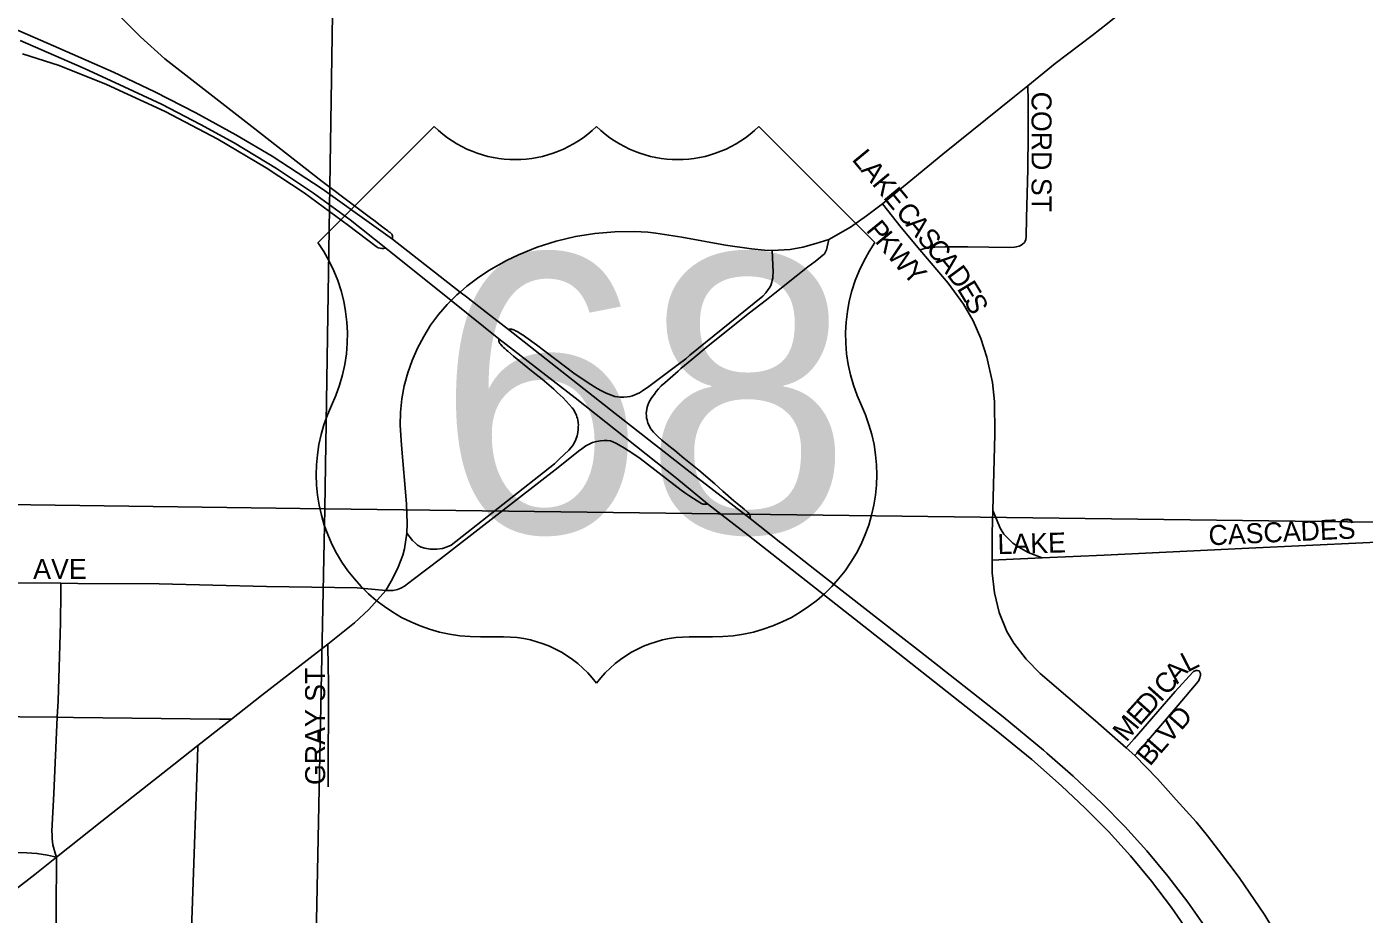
# Model space of a CAD drawing. Extents: x 0 to 68, y 0 to 52.9.
# Drawn here: x 41.67 to 42.505, y 40.366 to 40.921 of the extents above; entities that cross this region are included whole.
import ezdxf

# ---------------------------------------------------------------- set-up
doc = ezdxf.new("R2010")
doc.units = 0
doc.layers.add('Default', color=7, linetype='Continuous')
doc.layers.add('GM_X_State_Route', color=7, linetype='Continuous')

msp = doc.modelspace()

# ---------------------------------------------------------------- linework, layer by layer
at = {"layer": 'Default'}
for p, q in [((41.92409, 40.85834), (41.85158, 40.78583)), ((42.19962, 40.78583), (42.12711, 40.85834)), ((41.95309, 40.5393), (41.96759, 40.5393)), ((42.08361, 40.5393), (42.09811, 40.5393))]:
    msp.add_line(p, q, dxfattribs=at)
for points in [[(41.10506, 41.94675), (41.87622, 41.93634), (41.85592, 40.61931), (41.10506, 40.62946)], [(41.8103, 40.85824), (41.75595, 40.90059), (41.74066, 40.91439), (41.72611, 40.92896), (41.71224, 40.9442), (41.70184, 40.95698), (41.69228, 40.97039), (41.6835, 40.98434), (41.67743, 40.99509), (41.67196, 41.00616), (41.66553, 41.02132), (41.6622, 41.02928), (41.65923, 41.03743), (41.65561, 41.04891), (41.65231, 41.06176), (41.64933, 41.07672), (41.64711, 41.09293), (41.64541, 41.10932), (41.64438, 41.12577), (41.64394, 41.14636), (41.64444, 41.1661), (41.64451, 41.17742), (41.64564, 41.21171)], [(42.29505, 40.88376), (42.31219, 40.89769), (42.33529, 40.91526), (42.34493, 40.92274), (42.45334, 41.0106), (42.49482, 41.0441), (42.51495, 41.06071)], [(41.89813, 40.7878), (41.87629, 40.8034), (41.85426, 40.81934), (41.82295, 40.83972), (41.80032, 40.8531), (41.7752, 40.86688), (41.74968, 40.87989), (41.72382, 40.8922), (41.6864, 40.90876), (41.57753, 40.95631)], [(41.66687, 40.90374), (41.68976, 40.89646), (41.71949, 40.88447), (41.75597, 40.8677), (41.78896, 40.8504), (41.81915, 40.8325), (41.84298, 40.81673), (41.87054, 40.79641), (41.88801, 40.78328), (41.88926, 40.78253), (41.89034, 40.78224), (41.89151, 40.78209), (41.8928, 40.78209), (41.89402, 40.78224)], [(42.20434, 40.81), (42.21046, 40.81499), (42.24207, 40.84093), (42.28672, 40.87699), (42.29505, 40.88376)], [(42.22761, 40.7811), (42.23235, 40.78242), (42.23498, 40.7828), (42.23692, 40.78293), (42.2432, 40.78298), (42.25754, 40.78312), (42.28383, 40.78263), (42.28674, 40.78278), (42.28793, 40.78298), (42.28972, 40.78345), (42.29088, 40.78407), (42.29189, 40.78477), (42.29302, 40.78586), (42.29352, 40.78655), (42.29383, 40.78764), (42.29406, 40.7895), (42.29429, 40.8009), (42.29504, 40.83166), (42.29535, 40.85346), (42.29526, 40.87437), (42.29505, 40.88376)], [(41.89813, 40.7878), (41.89816, 40.78865), (41.89812, 40.78932), (41.89803, 40.78991), (41.89786, 40.79048), (41.89763, 40.79096), (41.89723, 40.79145), (41.89661, 40.79195), (41.89614, 40.79233), (41.89522, 40.79305), (41.89283, 40.79477), (41.8904, 40.79662), (41.8864, 40.79976), (41.88446, 40.80128), (41.87448, 40.80872), (41.85424, 40.82399), (41.8103, 40.85824)], [(42.17071, 40.78759), (42.18435, 40.7954), (42.19436, 40.80237), (42.20434, 40.81)], [(42.22761, 40.7811), (42.21606, 40.7952), (42.20434, 40.81)], [(41.94431, 40.75184), (41.94051, 40.75479), (41.89813, 40.7878)], [(41.90704, 40.60417), (41.90738, 40.6102), (41.90694, 40.62239), (41.90365, 40.65917), (41.90302, 40.67153), (41.90317, 40.67981), (41.90396, 40.68807), (41.90549, 40.69624), (41.90769, 40.70424), (41.91047, 40.71206), (41.91377, 40.71966), (41.91761, 40.72701), (41.92196, 40.73408), (41.92688, 40.74078), (41.93233, 40.74706), (41.93474, 40.74952), (41.93826, 40.75296), (41.94051, 40.75479), (41.94458, 40.75846), (41.95128, 40.76357), (41.95828, 40.76827), (41.96927, 40.77455), (41.97685, 40.77816), (41.98849, 40.7829), (42.00033, 40.78665), (42.01239, 40.78951), (42.02463, 40.79144), (42.03698, 40.79248), (42.04937, 40.79264), (42.05763, 40.7922), (42.06261, 40.79159), (42.07901, 40.78905), (42.10628, 40.78413), (42.12246, 40.78182), (42.13057, 40.78104), (42.13528, 40.78082)], [(42.12165, 40.61325), (42.12162, 40.61387), (42.12161, 40.61446), (42.12158, 40.61483), (42.12152, 40.61515), (42.12146, 40.61535), (42.12136, 40.61559), (42.1212, 40.61588), (42.12101, 40.61617), (42.1208, 40.61642), (42.12052, 40.61671), (42.12016, 40.61707), (42.11969, 40.61743), (42.11782, 40.61901), (42.11445, 40.6218), (42.1115, 40.62438), (42.10453, 40.63043), (42.09953, 40.63486), (42.08948, 40.64343), (42.08008, 40.651), (42.07447, 40.65573), (42.07074, 40.65866), (42.06643, 40.66225), (42.06386, 40.66444), (42.06242, 40.66587), (42.06115, 40.66725), (42.06014, 40.66852), (42.0592, 40.66994), (42.05845, 40.67135), (42.05778, 40.6729), (42.05717, 40.67485), (42.0569, 40.67605), (42.05676, 40.67752), (42.05672, 40.67916), (42.05698, 40.68143), (42.05729, 40.6829), (42.05772, 40.68417), (42.0584, 40.68575), (42.05914, 40.68712), (42.05982, 40.68833), (42.06087, 40.68981), (42.06177, 40.69107), (42.06292, 40.69265), (42.06438, 40.69434), (42.06607, 40.69611), (42.0682, 40.69808), (42.07655, 40.70544), (42.0783, 40.70695), (42.08282, 40.7107), (42.08511, 40.71268), (42.09541, 40.72115), (42.12122, 40.74173), (42.1318, 40.75004), (42.13707, 40.754), (42.15033, 40.76478), (42.15761, 40.7706), (42.16219, 40.77386), (42.16799, 40.77859), (42.16939, 40.78122), (42.17071, 40.78759)], [(42.13528, 40.78082), (42.1467, 40.78141), (42.15462, 40.78285), (42.16256, 40.7851), (42.17071, 40.78759)], [(42.39652, 40.35318), (42.38488, 40.37012), (42.37246, 40.38651), (42.35931, 40.40233), (42.34548, 40.41752), (42.33103, 40.43215), (42.31608, 40.44624), (42.29758, 40.46252), (42.2754, 40.4808), (42.21418, 40.52902), (42.12068, 40.60253), (42.09504, 40.62251), (42.07583, 40.63815), (42.01227, 40.68863), (41.96459, 40.72548), (41.93474, 40.74952), (41.89402, 40.78224)], [(42.13528, 40.78082), (42.13598, 40.76718), (42.13582, 40.76463), (42.13575, 40.76353), (42.13546, 40.76217), (42.13518, 40.76095), (42.13467, 40.75942), (42.13404, 40.75816), (42.13297, 40.75632), (42.13144, 40.75432), (42.1296, 40.75232), (42.08391, 40.71531), (42.08135, 40.71316), (42.07665, 40.70946), (42.05835, 40.69573), (42.05435, 40.69302), (42.0525, 40.69188), (42.04952, 40.69046), (42.04809, 40.68996), (42.04645, 40.68949), (42.04473, 40.68925), (42.04272, 40.6891), (42.04046, 40.68918), (42.0387, 40.68932), (42.03707, 40.6896), (42.03432, 40.69051), (42.03167, 40.69163), (42.02869, 40.693), (42.02594, 40.69452), (42.02031, 40.69801), (42.0115, 40.70412), (41.98804, 40.72172), (41.98148, 40.72655), (41.97971, 40.72777), (41.97793, 40.72891), (41.97641, 40.72988), (41.97506, 40.73059), (41.97446, 40.73088), (41.97333, 40.73132), (41.97296, 40.73143), (41.97241, 40.73154), (41.97182, 40.7316), (41.97127, 40.73157), (41.97054, 40.7314)], [(42.27321, 40.61828), (42.2746, 40.66595), (42.27427, 40.68633), (42.27296, 40.69836), (42.26949, 40.71415), (42.26576, 40.72569), (42.26091, 40.73675), (42.25489, 40.74722), (42.24545, 40.76044), (42.22761, 40.7811)], [(41.9569, 40.74203), (41.94431, 40.75184)], [(42.14132, 40.59768), (42.14077, 40.5981), (42.12165, 40.61325), (42.08902, 40.63853), (42.03717, 40.67885), (41.97054, 40.7314), (41.9569, 40.74203)], [(41.96459, 40.72548), (41.96456, 40.72497), (41.96462, 40.72423), (41.96467, 40.72389), (41.96474, 40.72365), (41.96484, 40.72335), (41.96502, 40.72304), (41.96524, 40.72272), (41.96572, 40.72208), (41.96665, 40.72098), (41.96741, 40.72021), (41.96824, 40.71943), (41.96936, 40.71846), (41.9701, 40.71775), (41.97373, 40.71481), (41.98605, 40.70462), (41.99157, 40.70025), (41.99896, 40.69409), (42.00109, 40.69207), (42.0048, 40.68869), (42.00674, 40.68664), (42.00862, 40.6846), (42.0105, 40.68239), (42.01137, 40.68121), (42.01191, 40.68019), (42.01245, 40.67917), (42.01308, 40.67772), (42.01338, 40.67684), (42.01363, 40.67583), (42.01385, 40.67491), (42.01411, 40.67299), (42.01427, 40.6717), (42.01422, 40.67045), (42.01411, 40.66889), (42.01384, 40.66706), (42.01344, 40.66502), (42.01261, 40.66255), (42.01157, 40.66036), (42.01051, 40.65868), (42.00828, 40.65602), (42.00238, 40.65058), (41.99931, 40.64747), (41.93485, 40.59664), (41.93221, 40.59544), (41.92932, 40.59447), (41.92574, 40.59406), (41.92383, 40.59403), (41.92171, 40.59414), (41.91833, 40.59464), (41.91603, 40.59535), (41.91385, 40.59661), (41.91241, 40.59776), (41.9106, 40.59952), (41.90704, 40.60417)], [(41.89399, 40.56831), (41.89664, 40.56817), (41.8986, 40.56831), (41.90131, 40.56879), (41.90342, 40.5696), (41.90572, 40.57103), (41.91108, 40.57503), (41.92817, 40.58798), (41.93747, 40.59539), (42.00164, 40.64521), (42.01429, 40.65532), (42.0165, 40.6569), (42.01897, 40.65866), (42.02095, 40.65978), (42.02312, 40.6607), (42.02561, 40.6614), (42.02811, 40.66185), (42.03029, 40.66206), (42.03237, 40.662), (42.03425, 40.66172), (42.03585, 40.66115), (42.03765, 40.66031), (42.0395, 40.65936), (42.04307, 40.65722), (42.0471, 40.6548), (42.05295, 40.6507), (42.07857, 40.63104), (42.08142, 40.62896), (42.0834, 40.62758), (42.08628, 40.62569), (42.08845, 40.62422), (42.09008, 40.62322), (42.09089, 40.62279), (42.09153, 40.62251), (42.09225, 40.62227), (42.0927, 40.62217), (42.09308, 40.62214), (42.09367, 40.62217), (42.09438, 40.6223), (42.09504, 40.62251)], [(42.27277, 40.58723), (42.27281, 40.60428), (42.27321, 40.61828)], [(42.27321, 40.61828), (42.27558, 40.61274), (42.27791, 40.60721), (42.2802, 40.60351), (42.28327, 40.60039), (42.28582, 40.59773), (42.28947, 40.59524), (42.29528, 40.59197), (42.304, 40.58857)], [(41.89399, 40.56831), (41.89812, 40.57557), (41.90175, 40.58278), (41.90454, 40.59033), (41.90558, 40.59421), (41.90704, 40.60417)], [(42.304, 40.58857), (42.34283, 40.59023), (42.43328, 40.59463), (42.54003, 40.59972), (42.59753, 40.60165), (42.63449, 40.60187), (42.68379, 40.60105), (42.73268, 40.59881), (42.84822, 40.59108)], [(42.16213, 40.58142), (42.14132, 40.59768)], [(42.35658, 40.46994), (42.33737, 40.48675), (42.30292, 40.51634), (42.29411, 40.52532), (42.28635, 40.53536), (42.28205, 40.54269), (42.27727, 40.5545), (42.27428, 40.56682), (42.27276, 40.57934), (42.27277, 40.58723)], [(42.27277, 40.58723), (42.27691, 40.58741), (42.304, 40.58857)], [(42.21416, 40.5408), (42.16213, 40.58142)], [(41.53021, 40.57232), (41.55608, 40.57233), (41.58259, 40.57315), (41.69092, 40.57273)], [(41.68868, 40.48905), (41.68911, 40.49922), (41.69057, 40.54794), (41.69084, 40.56676), (41.69092, 40.57273)], [(41.69092, 40.57273), (41.70157, 40.57269), (41.75225, 40.57244), (41.81935, 40.57075), (41.87601, 40.56982), (41.89399, 40.56831)], [(41.85763, 40.53462), (41.87439, 40.54812), (41.88336, 40.55637), (41.89399, 40.56831)], [(42.30696, 40.4666), (42.30498, 40.46834), (42.27966, 40.48919), (42.22813, 40.52989), (42.21416, 40.5408)], [(41.79746, 40.48775), (41.81634, 40.5026), (41.85763, 40.53462)], [(41.85798, 40.4456), (41.85812, 40.51167), (41.85794, 40.51982), (41.85763, 40.53462)], [(42.35658, 40.46994), (42.36153, 40.47561), (42.38725, 40.50507), (42.39823, 40.51725), (42.39864, 40.51757), (42.39914, 40.51786), (42.3996, 40.51802), (42.40005, 40.51815), (42.40049, 40.51822), (42.40111, 40.51825), (42.40226, 40.51793)], [(42.36202, 40.46517), (42.36584, 40.46934), (42.38905, 40.49658), (42.40147, 40.51127), (42.40195, 40.51204), (42.40227, 40.51265), (42.40268, 40.51364), (42.40291, 40.51469), (42.40297, 40.51521), (42.40299, 40.51573), (42.40293, 40.51641), (42.40283, 40.51688), (42.40226, 40.51793)], [(41.52812, 40.49024), (41.57166, 40.49002), (41.68868, 40.48905)], [(41.6882, 40.40146), (41.68731, 40.404), (41.68623, 40.40789), (41.68597, 40.40932), (41.68564, 40.41123), (41.68553, 40.41306), (41.68542, 40.41552), (41.68531, 40.4179), (41.68652, 40.4414), (41.68868, 40.48905)], [(41.68868, 40.48905), (41.69885, 40.48896), (41.79011, 40.48784), (41.79746, 40.48775)], [(41.7765, 40.47126), (41.79746, 40.48775)], [(41.6882, 40.40146), (41.7164, 40.42397), (41.76153, 40.45948), (41.7765, 40.47126)], [(41.7652, 40.24142), (41.76698, 40.24298), (41.76801, 40.24476), (41.76874, 40.24622), (41.76916, 40.24768), (41.76947, 40.24944), (41.76968, 40.25121), (41.76978, 40.25329), (41.76999, 40.25746), (41.77237, 40.34216), (41.77242, 40.35038), (41.77314, 40.37396), (41.77622, 40.46316), (41.7765, 40.47126)], [(42.36202, 40.46517), (42.35658, 40.46994)], [(42.49024, 39.94586), (42.49201, 40.02985), (42.49218, 40.07088), (42.49152, 40.09956), (42.48992, 40.12408), (42.48695, 40.14845), (42.48293, 40.1727), (42.47879, 40.19276), (42.47386, 40.21264), (42.4693, 40.22836), (42.46276, 40.24775), (42.45536, 40.26683), (42.44707, 40.28554), (42.43803, 40.30392), (42.42835, 40.32196), (42.41792, 40.33959), (42.40682, 40.35679), (42.39502, 40.37352), (42.38254, 40.38976), (42.36948, 40.40552), (42.35575, 40.4207), (42.34137, 40.43528), (42.32346, 40.4521), (42.30696, 40.4666)], [(42.47087, 40.31515), (42.45587, 40.34416), (42.44328, 40.36521), (42.42711, 40.38885), (42.41432, 40.40602), (42.40732, 40.41495), (42.40023, 40.42361), (42.38792, 40.43729), (42.37609, 40.45046), (42.36202, 40.46517)], [(41.52577, 40.40675), (41.6283, 40.40493), (41.66959, 40.40435), (41.67591, 40.40385), (41.68255, 40.4027), (41.6882, 40.40146)], [(41.65223, 40.37333), (41.67472, 40.3907), (41.6882, 40.40146)], [(41.68581, 40.24125), (41.68659, 40.28801), (41.68743, 40.32207), (41.68803, 40.36782), (41.6882, 40.40146)]]:
    msp.add_lwpolyline(points, dxfattribs=at)
for points in [[(41.87622, 41.93634), (43.20282, 41.92092), (43.18298, 40.60237), (41.85592, 40.61931)], [(43.18298, 40.60237), (43.18329, 40.58736), (43.1609, 39.26536), (41.82896, 39.29088), (41.85592, 40.61931)]]:
    msp.add_lwpolyline(points, close=True, dxfattribs=at)
for centre, radius, start, end in [((41.97484, 40.91012), 0.07251, 225.573, 314.427), ((42.07636, 40.91012), 0.07251, 225.573, 314.427), ((41.76842, 40.7276), 0.10151, 334.54712, 35.00093), ((42.28278, 40.7276), 0.10151, 144.99907, 205.45288), ((41.95196, 40.6408), 0.10151, 154.83192, 270.63826), ((42.09924, 40.6408), 0.10151, 269.36174, 25.16808), ((41.96759, 40.46679), 0.07251, 36.8699, 90), ((42.08361, 40.46679), 0.07251, 90, 143.1301)]:
    msp.add_arc(centre, radius, start, end, dxfattribs=at)
at = {"layer": 'GM_X_State_Route'}
msp.add_lwpolyline([(41.66553, 40.91206), (41.70421, 40.8951), (41.7084, 40.89327), (41.73049, 40.88305), (41.75376, 40.87234), (41.77818, 40.8595), (41.7991, 40.84805), (41.82565, 40.83193), (41.84869, 40.81656), (41.87173, 40.7999), (41.89402, 40.78224)], dxfattribs=at)

# ---------------------------------------------------------------- texts
at = {"layer": 'Default'}
for s, rotation, p in [('CORD ST', 270, (42.29745, 40.88007)), ('L', 309.54319, (42.18473, 40.83755)), ('A', 309.53696, (42.19033, 40.83077)), ('K', 309.5352, (42.19733, 40.82228)), ('E', 309.54319, (42.20433, 40.8138)), ('C', 309.54971, (42.21204, 40.80446)), ('P', 309.29134, (42.19356, 40.79329)), ('A', 309.55109, (42.21835, 40.79683)), ('S', 309.5258, (42.22535, 40.78835)), ('K', 309.54331, (42.19917, 40.78643)), ('W', 310.9939, (42.20639, 40.77769)), ('C', 309.54971, (42.23095, 40.78155)), ('A', 309.53696, (42.23726, 40.77392)), ('Y', 313.90518, (42.21623, 40.76639)), ('D', 306.49828, (42.24415, 40.76558)), ('E', 301.15116, (42.25052, 40.75699)), ('S', 296.41843, (42.25494, 40.7497)), ('CASCADES', 2.75597, (42.40831, 40.59642)), ('LAKE', 1.54736, (42.27634, 40.59092)), ('AVE', 0.00001, (41.6736, 40.57552)), ('L', 27.23693, (42.39486, 40.51684)), ('GRAY ST', 90, (41.85605, 40.44667)), ('A', 48.15411, (42.38847, 40.50938)), ('C', 48.17864, (42.38187, 40.502)), ('D', 48.15411, (42.37086, 40.4897)), ('I', 48.16943, (42.3782, 40.4979)), ('E', 48.3256, (42.36502, 40.48314)), ('D', 48.18497, (42.39089, 40.48019)), ('M', 50.74006, (42.35675, 40.47302)), ('V', 48.20126, (42.38356, 40.47199)), ('B', 49.9333, (42.37143, 40.45789)), ('L', 48.59561, (42.37775, 40.46541))]:
    msp.add_text(s, height=0.0125, rotation=rotation, dxfattribs=at).set_placement(p)
msp.add_text('68', height=0.174024, dxfattribs=at).set_placement((41.92599, 40.60456))

doc.saveas('drawing.dxf')
